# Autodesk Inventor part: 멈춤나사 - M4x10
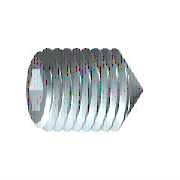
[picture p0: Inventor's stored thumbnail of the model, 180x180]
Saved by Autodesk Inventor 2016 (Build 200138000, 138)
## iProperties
Created: 2012-02
Part Number: 멈춤나사 - M4x10
Material: 강철, 연강
Description: 6각 소켓 머리 없는 멈춤 나사
Document SubType Name: Modeling
Standard: KS B 1028
Designer: mduedu
Standards Organization: KS
Language: ko-KR
Size Designation: 원추점 M4x10
Categories: <MemberInstance><Categories><Category DisplayName="조임쇠" InternalName="e4da775c-781d-43d5-af7c-5136215cf5a6" Mnemonic="FSTN"><Category DisplayName="볼트" InternalN
Density: 7.86 g/cm^3
Mass: 0.792069 g
Surface Area: 1.48192 cm^2
Volume: 0.100772 cm^3
Appearance: 강철
Author: mduedu
IsCustomPart: 1
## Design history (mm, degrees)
sketch "스케치1"
  geometry: L1 (0, 0)-(6.833, 0); L2 (10, 1.155)-(10, 2); L3 (10, 2)-(0, 2); L4 (10, 1.155)-(7.5, 1.155); L5 (7.5, 1.155)-(6.833, 0); L6 (0, -0.4)-(0, 2.4) reference; L7 (0, 2)-(0, 0)
  constraints: 13 end point, 3 parallel, 1 collinear, 1 perpendicular, 1 point on line
  dimensions: "d0" = 2.5 distance of L2.start L4.end (= INTI); "d1" = 60 deg angle of L5 L1; "d2" = 4 diameter of L3 L1 (= NND); "d3" = 2.3094 diameter of L4 L1 (= 1.1547 x SW); "d5" = 10 distance from line of L2 L3.end (= NLG)
revolve "본체" sketch "스케치1" stored, may be unused: angle "d6" = 90 deg
sketch "스케치2"
  geometry: L1 (-0.577, 1)-(0.577, 1); L2 (0.577, 1)-(1.155, 0); L3 (1.155, 0)-(0.577, -1); L4 (0.577, -1)-(-0.577, -1); L5 (-0.577, -1)-(-1.155, 0); L6 (-1.155, 0)-(-0.577, 1); 3 further points
  constraints: 12 end point, 1 coincident, 1 horizontal, 13 other
extrude "슬롯" join sketch "스케치2" taper "d7" = 0 deg; stored distance "d21" = 10
workaxis "Work Axis1"
workplane "Work Plane1"
sketch "스케치4"
  geometry: L1 (-5, 0.2)-(-3.2, 2) reference; L2 (-5, -0.2)-(-3.2, -2) reference; L3 (-3.2, 2)-(-5.2, 0); L4 (-3.2, -2)-(-5.2, 0); 2 further points
  constraints: 4 end point, 2 collinear, 1 coincident
body "Solid1"
feature "스레드" dims "d12" = 10 (= NLG), "d13" = 0
chamfer "모따기1" distance "d8" = 1.8 (computed from NND, SPD, FAWI); stored, may be unused: angle "d9" = 45 deg (= FAWI), second distance "d34" = 1.8 (computed from NND, SPD, FAWI)
chamfer "모따기2" distance "d10" = 0.42941 (= -0.5 x GD1 + 0.5 x NND); stored, may be unused: angle "d11" = 45 deg (= FAWI), second distance "d35" = 0.42941 (= -0.5 x GD1 + 0.5 x NND)
other parameters: "NND" = 4 [user parameter; used in 5 equation terms], "NLG" = 10 [user parameter; used in 2 equation terms], "INTI" = 2.5 [user parameter; used in 1 equation term], "FAWI" = 45 deg [user parameter; used in 4 equation terms], "SW" = 2 [user parameter; used in 2 equation terms], "GD1" = 3.14117 (= THREADDIA - 1.2269 x PTC) [user parameter; used in 2 equation terms], "d4" = 0, "FAWI1" = 45 deg [user parameter], "SPD" = 0.4 [user parameter; used in 2 equation terms], "d36" = 0, "d37" = 0, "GUL" = 0.42941 (= 0.61345 x PTC) [user parameter], "TPU" = 14.28571 (computed from PTC) [user parameter], "TOA" = 30 deg [user parameter], "THREADDIA" = 4 [user parameter; used in 1 equation term], "PTC" = 0.7 [user parameter; used in 4 equation terms], "GAL" = 0.42941 (= 0.61345 x PTC) [user parameter], "E0" = 2.31 (= 1.155 x SW) [user parameter]
